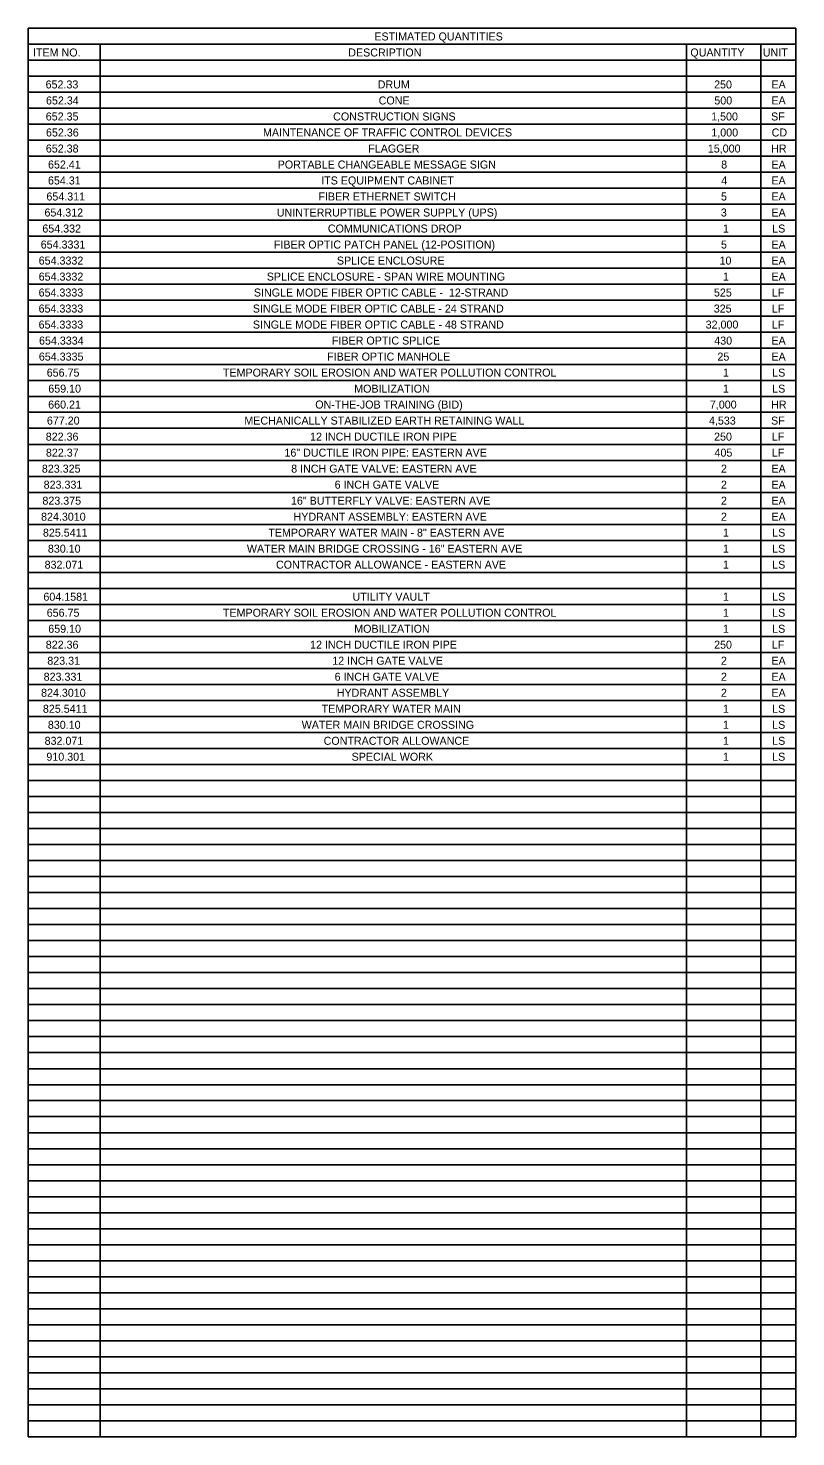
# Model space of a CAD drawing. Extents: x -18.7 to 5.6, y -2.7 to 5.1.
# Drawn here: x -5.186 to -4.242, y -0.314 to 1.418 of the extents above; entities that cross this region are included whole.
import ezdxf

# ---------------------------------------------------------------- set-up
doc = ezdxf.new("R2010")
doc.units = 0
doc.layers.add('ANNOTATION', color=7, linetype='Continuous')
doc.layers.add('BORDER', color=7, linetype='Continuous')

msp = doc.modelspace()

# ---------------------------------------------------------------- linework, layer by layer
at = {"layer": 'BORDER'}
for p, q in [((-5.186, 1.3986), (-4.2418, 1.3986)), ((-5.0975, 1.3986), (-5.0975, -0.314)), ((-4.3761, 1.3986), (-4.3761, -0.314)), ((-4.2848, 1.3986), (-4.2848, -0.314)), ((-5.186, 1.3789), (-4.2418, 1.3789)), ((-5.186, 1.3593), (-4.2418, 1.3593)), ((-5.186, 1.3396), (-4.2418, 1.3396)), ((-5.186, 1.3199), (-4.2418, 1.3199)), ((-5.186, 1.3002), (-4.2418, 1.3002)), ((-5.186, 1.2805), (-4.2418, 1.2805)), ((-5.186, 1.2608), (-4.2418, 1.2608)), ((-5.186, 1.2411), (-4.2418, 1.2411)), ((-5.186, 1.2215), (-4.2418, 1.2215)), ((-5.186, 1.2018), (-4.2418, 1.2018)), ((-5.186, 1.1821), (-4.2418, 1.1821)), ((-5.186, 1.1624), (-4.2418, 1.1624)), ((-5.186, 1.1427), (-4.2418, 1.1427)), ((-5.186, 1.123), (-4.2418, 1.123)), ((-5.186, 1.1033), (-4.2418, 1.1033)), ((-5.186, 1.0837), (-4.2418, 1.0837)), ((-5.186, 1.064), (-4.2418, 1.064)), ((-5.186, 1.0443), (-4.2418, 1.0443)), ((-5.186, 1.0246), (-4.2418, 1.0246)), ((-5.186, 1.0049), (-4.2418, 1.0049)), ((-5.186, 0.9852), (-4.2418, 0.9852)), ((-5.186, 0.9655), (-4.2418, 0.9655)), ((-5.186, 0.9459), (-4.2418, 0.9459)), ((-5.186, 0.9262), (-4.2418, 0.9262)), ((-5.186, 0.9065), (-4.2418, 0.9065)), ((-5.186, 0.8868), (-4.2418, 0.8868)), ((-5.186, 0.8671), (-4.2418, 0.8671)), ((-5.186, 0.8474), (-4.2418, 0.8474)), ((-5.186, 0.8277), (-4.2418, 0.8277)), ((-5.186, 0.8081), (-4.2418, 0.8081)), ((-5.186, 0.7884), (-4.2418, 0.7884)), ((-5.186, 0.7687), (-4.2418, 0.7687)), ((-5.186, 0.749), (-4.2418, 0.749)), ((-5.186, 0.7293), (-4.2418, 0.7293)), ((-5.186, 0.7096), (-4.2418, 0.7096)), ((-5.186, 0.6899), (-4.2418, 0.6899)), ((-5.186, 0.6703), (-4.2418, 0.6703)), ((-5.186, 0.6506), (-4.2418, 0.6506)), ((-5.186, 0.6309), (-4.2418, 0.6309)), ((-5.186, 0.6112), (-4.2418, 0.6112)), ((-5.186, 0.5915), (-4.2418, 0.5915)), ((-5.186, 0.5718), (-4.2418, 0.5718)), ((-5.186, 0.5521), (-4.2418, 0.5521)), ((-5.186, 0.5324), (-4.2418, 0.5324)), ((-5.186, 0.5128), (-4.2418, 0.5128)), ((-5.186, 0.4931), (-4.2418, 0.4931)), ((-5.186, 0.4734), (-4.2418, 0.4734)), ((-5.186, 0.4537), (-4.2418, 0.4537)), ((-5.186, 0.434), (-4.2418, 0.434)), ((-5.186, 0.4143), (-4.2418, 0.4143)), ((-5.186, 0.3946), (-4.2418, 0.3946)), ((-5.186, 0.375), (-4.2418, 0.375)), ((-5.186, 0.3553), (-4.2418, 0.3553)), ((-5.186, 0.3356), (-4.2418, 0.3356)), ((-5.186, 0.3159), (-4.2418, 0.3159)), ((-5.186, 0.2962), (-4.2418, 0.2962)), ((-5.186, 0.2765), (-4.2418, 0.2765)), ((-5.186, 0.2568), (-4.2418, 0.2568)), ((-5.186, 0.2372), (-4.2418, 0.2372)), ((-5.186, 0.2175), (-4.2418, 0.2175)), ((-5.186, 0.1978), (-4.2418, 0.1978)), ((-5.186, 0.1781), (-4.2418, 0.1781)), ((-5.186, 0.1584), (-4.2418, 0.1584)), ((-5.186, 0.1387), (-4.2418, 0.1387)), ((-5.186, 0.119), (-4.2418, 0.119)), ((-5.186, 0.0994), (-4.2418, 0.0994)), ((-5.186, 0.0797), (-4.2418, 0.0797)), ((-5.186, 0.06), (-4.2418, 0.06)), ((-5.186, 0.0403), (-4.2418, 0.0403)), ((-5.186, 0.0206), (-4.2418, 0.0206)), ((-5.186, 0.0009), (-4.2418, 0.0009)), ((-5.186, -0.0188), (-4.2418, -0.0188)), ((-5.186, -0.0384), (-4.2418, -0.0384)), ((-5.186, -0.0581), (-4.2418, -0.0581)), ((-5.186, -0.0778), (-4.2418, -0.0778)), ((-5.186, -0.0975), (-4.2418, -0.0975)), ((-5.186, -0.1172), (-4.2418, -0.1172)), ((-5.186, -0.1369), (-4.2418, -0.1369)), ((-5.186, -0.1566), (-4.2418, -0.1566)), ((-5.186, -0.1762), (-4.2418, -0.1762)), ((-5.186, -0.1959), (-4.2418, -0.1959)), ((-5.186, -0.2156), (-4.2418, -0.2156)), ((-5.186, -0.2353), (-4.2418, -0.2353)), ((-5.186, -0.255), (-4.2418, -0.255)), ((-5.186, -0.2747), (-4.2418, -0.2747)), ((-5.186, -0.2944), (-4.2418, -0.2944)), ((-5.186, -0.314), (-4.2418, -0.314))]:
    msp.add_line(p, q, dxfattribs=at)
msp.add_lwpolyline([(-5.186, 1.4183), (-4.2418, 1.4183), (-4.2418, -0.314), (-5.186, -0.314)], close=True, dxfattribs=at)

# ---------------------------------------------------------------- texts
at = {"layer": 'ANNOTATION'}
for s, height, p in [('652.33', 0.00984, (-5.1646, 1.3442)), ('DRUM', 0.00984, (-4.7561, 1.3442)), ('250', 0.00984, (-4.3423, 1.3442)), ('EA', 0.00984, (-4.2718, 1.3442)), ('652.34', 0.00984, (-5.1641, 1.3245)), ('CONE', 0.00984, (-4.7549, 1.3245)), ('500', 0.00984, (-4.342, 1.3245)), ('EA', 0.00984, (-4.2718, 1.3245)), ('652.35', 0.00984, (-5.1644, 1.3048)), ('CONSTRUCTION SIGNS', 0.009843, (-4.8109, 1.3048)), ('1,500', 0.00984, (-4.3459, 1.3048)), ('SF', 0.00984, (-4.2722, 1.3048)), ('652.36', 0.00984, (-5.1641, 1.2851)), ('MAINTENANCE OF TRAFFIC CONTROL DEVICES', 0.009843, (-4.8972, 1.2851)), ('1,000', 0.00984, (-4.3457, 1.2851)), ('CD', 0.00984, (-4.2715, 1.2851)), ('652.38', 0.00984, (-5.1643, 1.2654)), ('FLAGGER', 0.00984, (-4.7677, 1.2654)), ('15,000', 0.00984, (-4.35, 1.2654)), ('HR', 0.00984, (-4.2722, 1.2654)), ('652.41', 0.00984, (-5.1616, 1.2457)), ('PORTABLE CHANGEABLE MESSAGE SIGN', 0.009843, (-4.8791, 1.2457)), ('8', 0.00984, (-4.3336, 1.2457)), ('EA', 0.00984, (-4.2718, 1.2457)), ('654.31', 0.00984, (-5.1617, 1.2261)), ('ITS EQUIPMENT CABINET  ', 0.009843, (-4.8256, 1.2261)), ('4', 0.00984, (-4.3335, 1.2261)), ('EA', 0.00984, (-4.2718, 1.2261)), ('654.311', 0.00984, (-5.1636, 1.2064)), ('FIBER ETHERNET SWITCH ', 0.009843, (-4.829, 1.2064)), ('5', 0.00984, (-4.3338, 1.2064)), ('EA', 0.00984, (-4.2718, 1.2064)), ('654.312', 0.00984, (-5.166, 1.1867)), ('UNINTERRUPTIBLE POWER SUPPLY (UPS)', 0.009843, (-4.8802, 1.1867)), ('3', 0.00984, (-4.334, 1.1867)), ('EA', 0.00984, (-4.2718, 1.1867)), ('654.332', 0.00984, (-5.1686, 1.167)), ('COMMUNICATIONS DROP', 0.009843, (-4.8174, 1.167)), ('1', 0.00984, (-4.3315, 1.167)), ('LS', 0.00984, (-4.2708, 1.167)), ('654.3331', 0.00984, (-5.1706, 1.1473)), ('FIBER OPTIC PATCH PANEL (12-POSITION)', 0.009843, (-4.8838, 1.1473)), ('5', 0.00984, (-4.3338, 1.1473)), ('EA', 0.00984, (-4.2718, 1.1473)), ('654.3332', 0.00984, (-5.1731, 1.1276)), ('SPLICE ENCLOSURE', 0.009843, (-4.8063, 1.1276)), ('10', 0.00984, (-4.3356, 1.1276)), ('EA', 0.00984, (-4.2718, 1.1276)), ('654.3332', 0.00984, (-5.1731, 1.1079)), ('SPLICE ENCLOSURE - SPAN WIRE MOUNTING', 0.009843, (-4.8926, 1.1079)), ('1', 0.00984, (-4.3315, 1.1079)), ('EA', 0.00984, (-4.2718, 1.1079)), ('654.3333', 0.00984, (-5.1732, 1.0883)), ('SINGLE MODE FIBER OPTIC CABLE -  12-STRAND', 0.009843, (-4.9084, 1.0883)), ('525', 0.00984, (-4.3425, 1.0883)), ('LF', 0.00984, (-4.2712, 1.0883)), ('654.3333', 0.00984, (-5.1732, 1.0686)), ('SINGLE MODE FIBER OPTIC CABLE - 24 STRAND', 0.009843, (-4.9097, 1.0686)), ('325', 0.00984, (-4.3427, 1.0686)), ('LF', 0.00984, (-4.2712, 1.0686)), ('654.3333', 0.00984, (-5.1732, 1.0489)), ('SINGLE MODE FIBER OPTIC CABLE - 48 STRAND', 0.009843, (-4.9096, 1.0489)), ('32,000', 0.00984, (-4.3527, 1.0489)), ('LF', 0.00984, (-4.2712, 1.0489)), ('654.3334', 0.00984, (-5.1727, 1.0292)), ('FIBER OPTIC SPLICE ', 0.009843, (-4.8124, 1.0292)), ('430', 0.00984, (-4.3421, 1.0292)), ('EA', 0.00984, (-4.2718, 1.0292)), ('654.3335', 0.00984, (-5.1729, 1.0095)), ('FIBER OPTIC MANHOLE ', 0.009843, (-4.8183, 1.0095)), ('25', 0.00984, (-4.3382, 1.0095)), ('EA', 0.00984, (-4.2718, 1.0095)), ('656.75', 0.00984, (-5.1632, 0.9898)), ('TEMPORARY SOIL EROSION AND WATER POLLUTION CONTROL', 0.009843, (-4.9465, 0.9898)), ('1', 0.00984, (-4.3315, 0.9898)), ('LS', 0.00984, (-4.2708, 0.9898)), ('659.10', 0.00984, (-5.1613, 0.9701)), ('MOBILIZATION', 0.009843, (-4.785, 0.9701)), ('1', 0.00984, (-4.3315, 0.9701)), ('LS', 0.00984, (-4.2708, 0.9701)), ('660.21', 0.00984, (-5.1614, 0.9505)), ('ON-THE-JOB TRAINING (BID)', 0.009843, (-4.8329, 0.9505)), ('7,000', 0.00984, (-4.3475, 0.9505)), ('HR', 0.00984, (-4.2722, 0.9505)), ('677.20', 0.00984, (-5.163, 0.9308)), ('MECHANICALLY STABILIZED EARTH RETAINING WALL', 0.009843, (-4.9201, 0.9308)), ('4,533', 0.00984, (-4.3486, 0.9308)), ('SF', 0.00984, (-4.2722, 0.9308)), ('822.36', 0.00984, (-5.1644, 0.9111)), ('12 INCH DUCTILE IRON PIPE', 0.009843, (-4.8393, 0.9111)), ('250', 0.00984, (-4.3423, 0.9111)), ('LF', 0.00984, (-4.2712, 0.9111)), ('822.37', 0.00984, (-5.1642, 0.8914)), ('16" DUCTILE IRON PIPE: EASTERN AVE', 0.009843, (-4.8708, 0.8914)), ('405', 0.00984, (-4.3418, 0.8914)), ('LF', 0.00984, (-4.2712, 0.8914)), ('823.325', 0.00984, (-5.1692, 0.8717)), ('8 INCH GATE VALVE: EASTERN AVE', 0.009843, (-4.8625, 0.8717)), ('2', 0.00984, (-4.3339, 0.8717)), ('EA', 0.00984, (-4.2718, 0.8717)), ('823.331', 0.00984, (-5.167, 0.852)), ('6 INCH GATE VALVE', 0.009843, (-4.8091, 0.852)), ('2', 0.00984, (-4.3339, 0.852)), ('EA', 0.00984, (-4.2718, 0.852)), ('823.375', 0.00984, (-5.1685, 0.8323)), ('16" BUTTERFLY VALVE: EASTERN AVE', 0.009843, (-4.8628, 0.8323)), ('2', 0.00984, (-4.3339, 0.8323)), ('EA', 0.00984, (-4.2718, 0.8323)), ('824.3010', 0.00984, (-5.1702, 0.8126)), ('HYDRANT ASSEMBLY: EASTERN AVE', 0.009843, (-4.8596, 0.8126)), ('2', 0.00984, (-4.3339, 0.8126)), ('EA', 0.00984, (-4.2718, 0.8126)), ('825.5411', 0.00984, (-5.1679, 0.793)), ('TEMPORARY WATER MAIN - 8" EASTERN AVE', 0.009843, (-4.8906, 0.793)), ('1', 0.00984, (-4.3315, 0.793)), ('LS', 0.00984, (-4.2708, 0.793)), ('830.10', 0.00984, (-5.1618, 0.7733)), ('WATER MAIN BRIDGE CROSSING - 16" EASTERN AVE', 0.009843, (-4.917, 0.7733)), ('1', 0.00984, (-4.3315, 0.7733)), ('LS', 0.00984, (-4.2708, 0.7733)), ('832.071', 0.00984, (-5.1658, 0.7536)), ('CONTRACTOR ALLOWANCE - EASTERN AVE', 0.009843, (-4.8812, 0.7536)), ('1', 0.00984, (-4.3315, 0.7536)), ('LS', 0.00984, (-4.2708, 0.7536)), ('604.1581', 0.00984, (-5.1673, 0.7142)), ('UTILITY VAULT', 0.009843, (-4.7871, 0.7142)), ('1', 0.00984, (-4.3315, 0.7142)), ('LS', 0.00984, (-4.2708, 0.7142)), ('656.75', 0.00984, (-5.1632, 0.6945)), ('TEMPORARY SOIL EROSION AND WATER POLLUTION CONTROL', 0.009843, (-4.9465, 0.6945)), ('1', 0.00984, (-4.3315, 0.6945)), ('LS', 0.00984, (-4.2708, 0.6945)), ('659.10', 0.00984, (-5.1613, 0.6748)), ('MOBILIZATION', 0.009843, (-4.785, 0.6748)), ('1', 0.00984, (-4.3315, 0.6748)), ('LS', 0.00984, (-4.2708, 0.6748)), ('822.36', 0.00984, (-5.1644, 0.6552)), ('12 INCH DUCTILE IRON PIPE', 0.009843, (-4.8393, 0.6552)), ('250', 0.00984, (-4.3423, 0.6552)), ('LF', 0.00984, (-4.2712, 0.6552)), ('823.31', 0.00984, (-5.1625, 0.6355)), ('12 INCH GATE VALVE', 0.009843, (-4.812, 0.6355)), ('2', 0.00984, (-4.3339, 0.6355)), ('EA', 0.00984, (-4.2718, 0.6355)), ('823.331', 0.00984, (-5.167, 0.6158)), ('6 INCH GATE VALVE', 0.009843, (-4.8091, 0.6158)), ('2', 0.00984, (-4.3339, 0.6158)), ('EA', 0.00984, (-4.2718, 0.6158)), ('824.3010', 0.00984, (-5.1702, 0.5961)), ('HYDRANT ASSEMBLY', 0.009843, (-4.8065, 0.5961)), ('2', 0.00984, (-4.3339, 0.5961)), ('EA', 0.00984, (-4.2718, 0.5961)), ('825.5411', 0.00984, (-5.1679, 0.5764)), ('TEMPORARY WATER MAIN', 0.009843, (-4.825, 0.5764)), ('1', 0.00984, (-4.3315, 0.5764)), ('LS', 0.00984, (-4.2708, 0.5764)), ('830.10', 0.00984, (-5.1618, 0.5567)), ('WATER MAIN BRIDGE CROSSING', 0.009843, (-4.8496, 0.5567)), ('1', 0.00984, (-4.3315, 0.5567)), ('LS', 0.00984, (-4.2708, 0.5567)), ('832.071', 0.00984, (-5.1658, 0.537)), ('CONTRACTOR ALLOWANCE', 0.009843, (-4.8226, 0.537)), ('1', 0.00984, (-4.3315, 0.537)), ('LS', 0.00984, (-4.2708, 0.537)), ('910.301', 0.00984, (-5.1636, 0.5174)), ('SPECIAL WORK', 0.009843, (-4.7882, 0.5174)), ('1', 0.00984, (-4.3315, 0.5174)), ('LS', 0.00984, (-4.2708, 0.5174))]:
    msp.add_text(s, height=height, dxfattribs=at).set_placement(p)
at = {"layer": 'BORDER'}
for s, height, p in [('ESTIMATED QUANTITIES', 0.009843, (-4.7602, 1.4032)), ('ITEM NO.', 0.00984, (-5.1801, 1.3835)), ('DESCRIPTION', 0.009843, (-4.7923, 1.3835)), ('QUANTITY', 0.00984, (-4.3715, 1.3835)), ('UNIT', 0.00984, (-4.2824, 1.3835))]:
    msp.add_text(s, height=height, dxfattribs=at).set_placement(p)

doc.saveas('drawing.dxf')
